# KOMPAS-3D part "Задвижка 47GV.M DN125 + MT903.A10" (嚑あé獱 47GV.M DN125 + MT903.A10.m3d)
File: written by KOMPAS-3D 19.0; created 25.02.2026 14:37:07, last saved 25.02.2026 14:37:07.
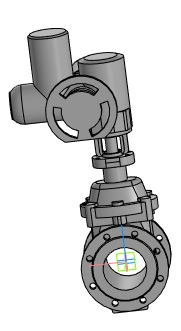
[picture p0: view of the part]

Document properties: Автор: Энергия; Полное имя файла: ..\..\47GVM\DR.47GVM.125.16.00.000\DR.47GVM.125.16.00.00 - Задвижка с обрезиненным клином DN125.a3d

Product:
- Part/product: Задвижка 47GV.M DN125 + MT903.A10
    Масса: 117.028
  - Component: Задвижка с обрезиненным клином DN125. Сборочный чертеж  | designation DR.47GVM.125.16.00.00СБ  | pos. 0  | Масса: 25.3494; Раздел спецификации: Документация; Форматы листов документа: 2xA3; source file: 47GV.M DN125\DR.47GVM.125.16.00.000 СБ - Задвижка с обрезиненным клином DN125.cdw

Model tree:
1. Операция без истории:1

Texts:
  Точка начала. Х
  Точка начала. Y
  Точка начала. Z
